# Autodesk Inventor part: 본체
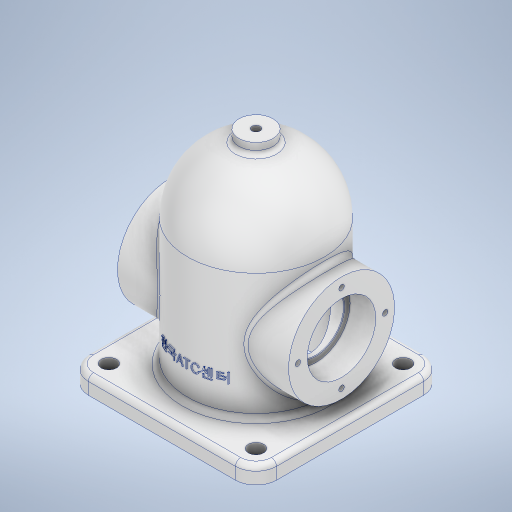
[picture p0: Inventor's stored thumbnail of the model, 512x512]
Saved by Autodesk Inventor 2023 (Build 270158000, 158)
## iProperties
Created: 2025-04
Part Number: 본체
Material: 알루미늄 6061
Document SubType Name: Modeling
Designer: User
Density: 2.7 g/cm^3
Appearance: 알루미늄 - 평지
Author: User
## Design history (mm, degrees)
sketch "스케치1"
  geometry: L1 (-55, 55)-(55, 55); L2 (55, 55)-(55, -55); L3 (55, -55)-(-55, -55); L4 (-55, -55)-(-55, 55); L5 (-55, 55)-(55, -55); L6 (55, 55)-(-55, -55); 1 further point
  constraints: 12 end point, 2 midpoint, 2 parallel, 1 horizontal, 1 perpendicular
  dimensions: "d0" = 110 distance of L2.end L3.end; "d1" = 110 distance of L1.end L2.end
extrude "돌출1" new body sketch "스케치1" distance "d2" = 10; taper "d3" = 0 deg
fillet "모깎기1" dims "d4" = 3
sketch "스케치2"
  geometry: C1 r 40 at (0, 0); 1 further point
  constraints: 1 centre point, 1 coincident
  dimensions: "d5" = 80 diameter of C1
extrude "돌출2" join sketch "스케치2" distance "d6" = 84; taper "d7" = 0 deg
node "작업 평면1"
sketch "스케치3"
  geometry: L1 (55, 0)-(-55, 0) reference; C1 r 31 at (0, 48); 1 further point
  constraints: 1 centre point, 1 vertical alignment
  dimensions: "d9" = 62 diameter of C1; "d10" = 48 distance from line of L1 C1.centre
extrude "돌출3" join sketch "스케치3" stored distance "d11" = 84; taper "d12" = 0 deg
sketch "스케치4" dims "d13" = 51
  geometry: L1 (-55, -48)-(55, -48) reference; 4 further points
  constraints: 3 vertical alignment, 1 midpoint, 2 other
  dimensions: "d14" = 48 distance from line of L1 point (0, 0)
hole "구멍1" sketch "스케치4" at (0, 25.5) diameter "d15" = 3.242; stored, may be unused: countersink angle "d19" = 90 deg, drill point angle "d21" = 118 deg; dims "d16" = 8, "d17" = 4, "d18" = 2, "d20" = 10
sketch "스케치5"
  geometry: L1 (84, -40)-(84, 40) reference; A1 r 40 centre (84, 0) between (84, -40) and (84, 40); 1 further point
  constraints: 2 point on circle, 1 centre point, 1 midpoint
revolve "회전1" sketch "스케치5" stored, may be unused: angle "d25" = 90 deg
sketch "스케치6"
  geometry: C1 r 32 at (0, 0); 1 further point
  constraints: 1 centre point, 1 coincident
  dimensions: "d26" = 64 diameter of C1
extrude "돌출4" cut sketch "스케치6" distance "d27" = 84; taper "d28" = 0 deg
sketch "스케치7"
  geometry: L1 (84, -32)-(84, 32) reference; A1 r 32 centre (84, 0) between (84, -32) and (84, 32); 2 further points
  constraints: 2 point on circle, 1 centre point, 1 midpoint
revolve "회전2" sketch "스케치7" stored, may be unused: angle "d29" = 90 deg
sketch "스케치8"
  geometry: L1 (-55, -48)-(55, -48) reference; C1 r 16.5 at (0, 0); 2 further points
  constraints: 1 centre point, 1 midpoint, 1 vertical alignment
  dimensions: "d30" = 33 diameter of C1; "d31" = 48 distance from line of L1 C1.centre
extrude "돌출5" cut sketch "스케치8" stored distance "d32" = 15; taper "d33" = 0 deg
node "작업 평면2"
fillet "모깎기2" dims "d45" = 3
fillet "모깎기3" dims "d46" = 3
sketch "스케치11"
  geometry: L1 (43, -43)-(-43, -43); L2 (-43, -43)-(-43, 43); L3 (-43, 43)-(43, 43); L4 (43, 43)-(43, -43); L5 (43, -43)-(-43, 43); L6 (-43, -43)-(43, 43); 5 further points
  constraints: 12 end point, 4 coincident, 2 midpoint, 2 parallel, 1 horizontal, 1 perpendicular
  dimensions: "d47" = 86 distance of L2.end L3.end; "d48" = 86 distance of L1.end L2.end
hole "구멍3" sketch "스케치11" at (-43, -43), (-43, 43), (43, 43), (43, -43) diameter "d49" = 9; stored, may be unused: countersink angle "d53" = 90 deg, drill point angle "d55" = 118 deg; dims "d50" = 6, "d51" = 4, "d52" = 2, "d54" = 13
fillet "모깎기4" dims "d56" = 12
sketch "스케치17"
  geometry: L1 (-43, -48)-(43, -48) reference; C1 r 20 at (0, 0); 2 further points
  constraints: 1 centre point, 1 midpoint, 1 vertical alignment
  dimensions: "d81" = 40 diameter of C1; "d82" = 48 distance from line of L1 C1.centre
extrude "돌출8" cut sketch "스케치17" distance "d83" = 15; taper "d84" = 0 deg
chamfer "모따기1" distance "d57" = 1; stored, may be unused: second distance "d58" = 2, angle "d59" = 45 deg
node "작업 평면3"
sketch "스케치12"
  geometry: C1 r 10 at (0, 0); 1 further point
  constraints: 1 centre point, 1 coincident
  dimensions: "d64" = 20 diameter of C1
extrude "돌출7" join sketch "스케치12" stored distance "d65" = 10; taper "d66" = 0 deg
fillet "모깎기5" dims "d67" = 3
sketch "스케치13"
  geometry: C1 r 10 at (0, 0) reference; 2 further points
  constraints: 1 coincident
hole "구멍4" sketch "스케치13" diameter "d69" = 4.917; stored, may be unused: countersink angle "d73" = 82 deg, drill point angle "d75" = 0 deg; dims "d70" = 13, "d71" = 3.023, "d72" = 2, "d74" = 13
node "작업 평면5"
sketch "스케치15"
  geometry: L1 (0, 43)-(0, -43) reference; 3 further points
  constraints: 1 horizontal alignment, 1 midpoint, 1 other
  dimensions: "d77" = 30 distance from line of L1 point (30, 0)
feature "엠보싱1" sketch "스케치15" dims "d78" = 0.5, "d79" = 0
chamfer "모따기3" distance "d85" = 0.3; stored, may be unused: second distance "d86" = 2, angle "d87" = 45 deg
node "솔리드1"
mirror "미러1"
pattern_circular "원형 패턴1" dims angle "d23" = 360 deg
mirror "미러2"
mirror "미러3"
mirror "미러4"
feature "A9D066F2-1C7D-4E18-AEED-F7BC21143FA4" dims "d49" = 9, "d50" = 6, "d51" = 4, "d52" = 2, "d53" = 90 deg, "d54" = 13, "d55" = 118 deg
other parameters: "d34" = 124, "d63" = 129
